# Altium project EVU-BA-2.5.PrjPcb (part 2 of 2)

## Sheet EVU-BA-2.5_Sheet4.SchDoc: EVU-BA-2.5
size A3; SheetNumber: 4; SheetTotal: 7; Prj: EVU-BA; Ver: 2.5; Ti: Kit Connectors
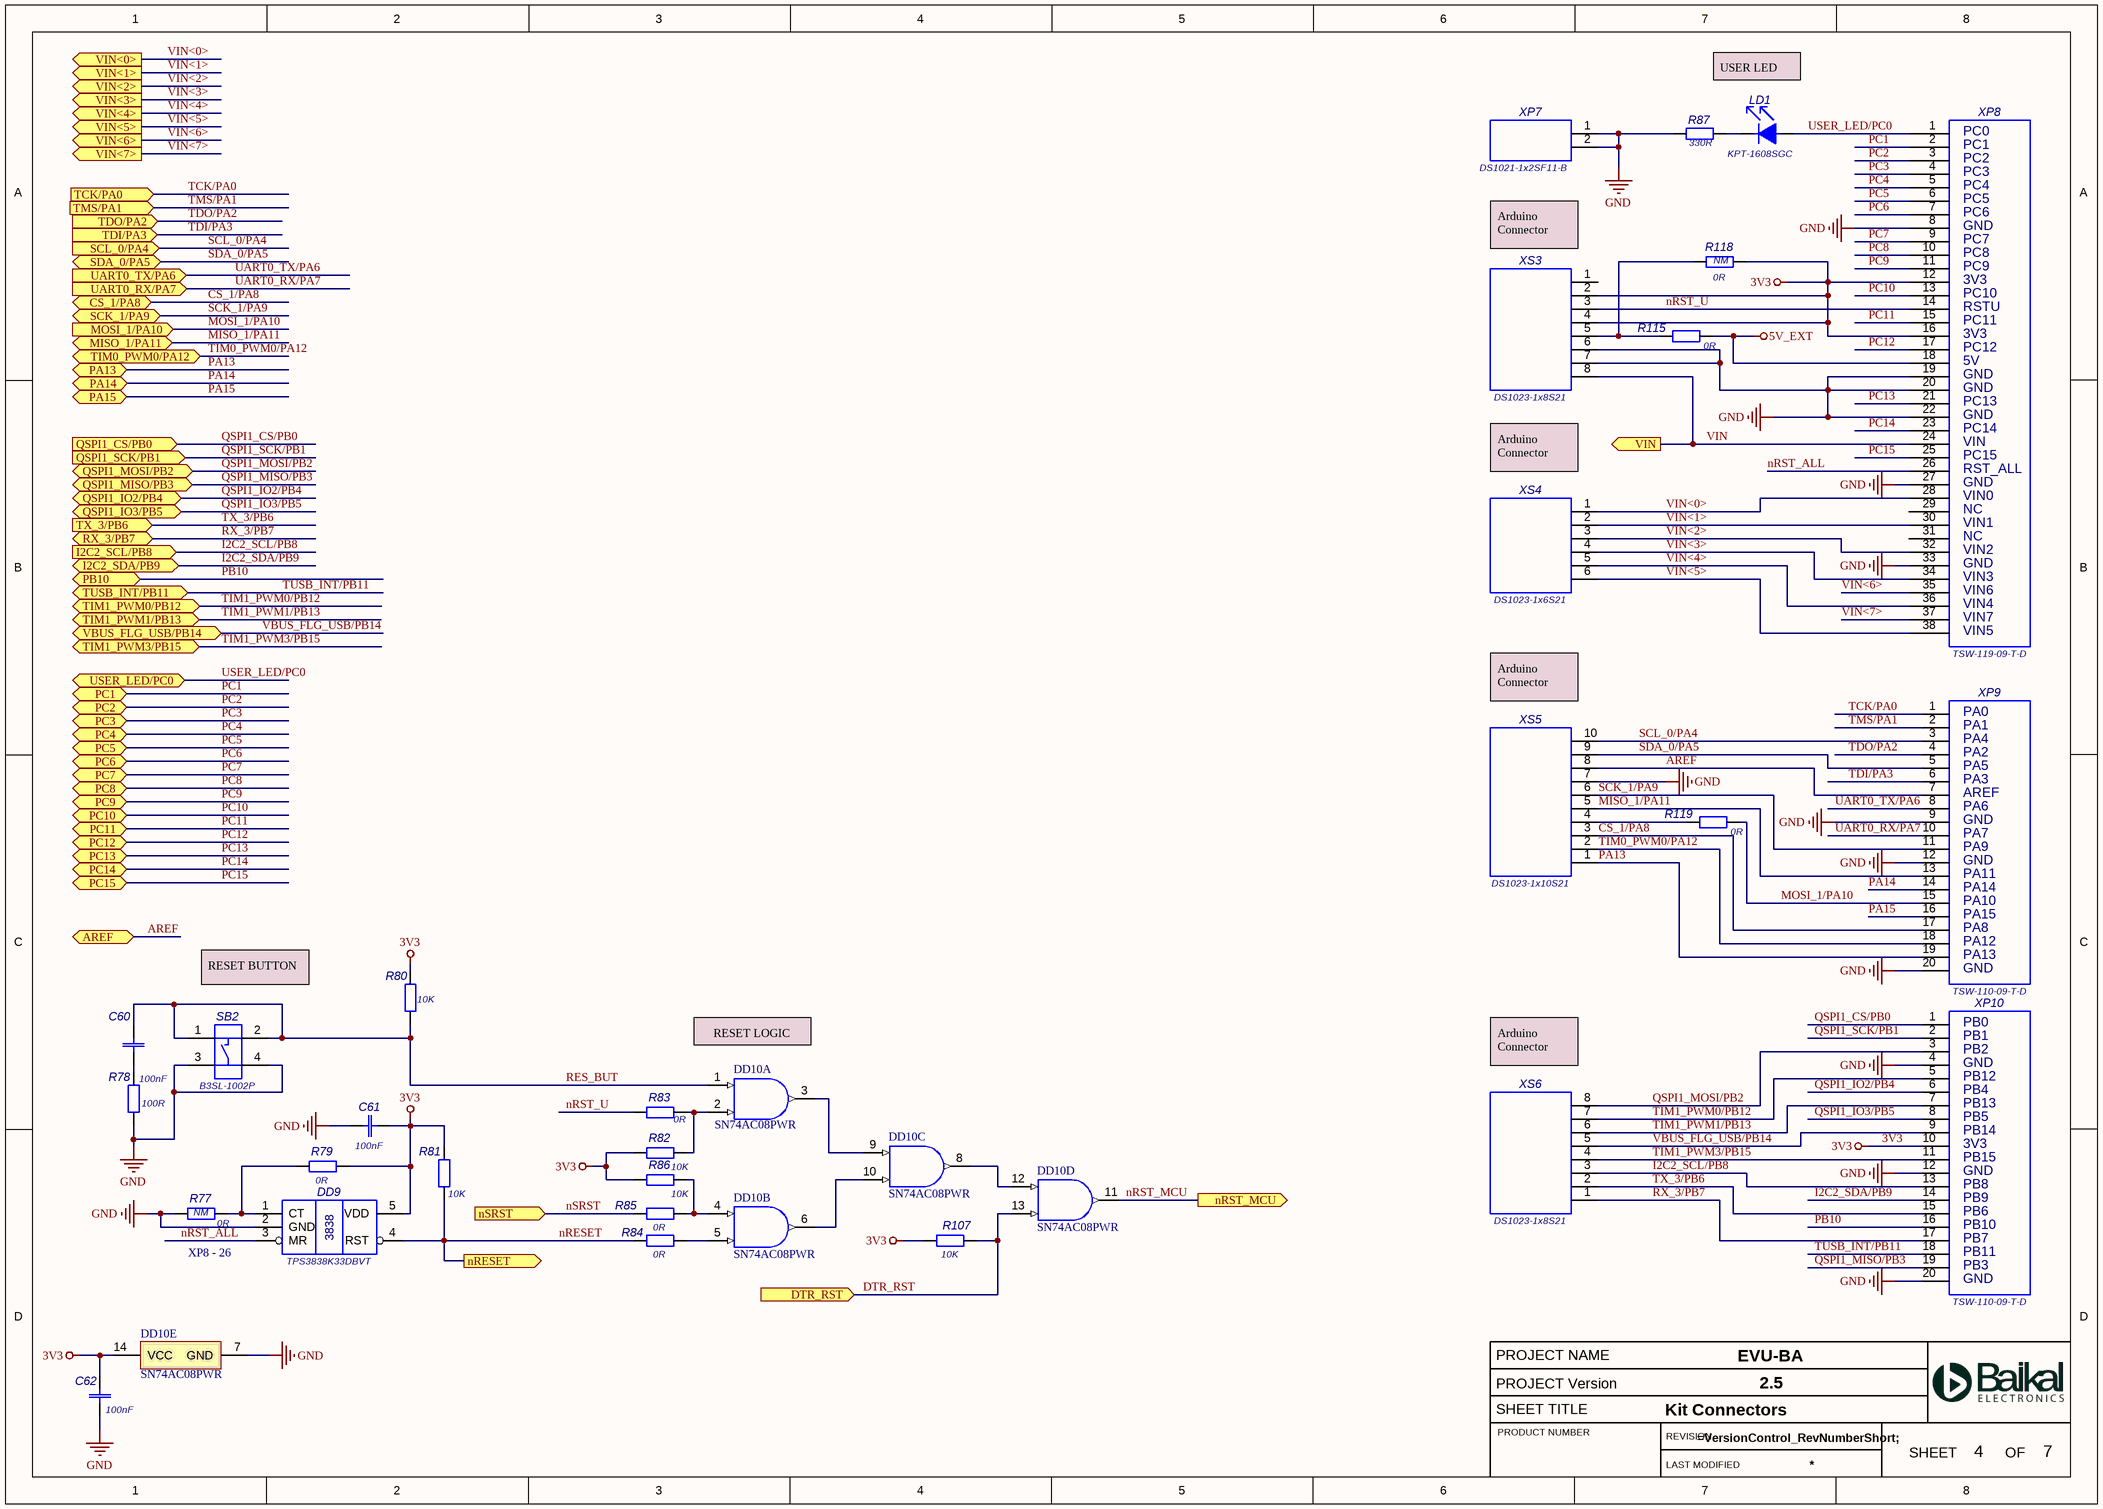
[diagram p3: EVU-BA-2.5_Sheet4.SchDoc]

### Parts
C60  value 100nF  [CAPC1608X80N]  (hidden comment: C0603C104K5RAC)
C61  value 100nF  [CAPC1608X80N]  (hidden comment: C0603C104K5RAC)
C62  value 100nF  [CAPC1608X80N]  (hidden comment: C0603C104K5RAC)
DD9  TPS3838K33DBVT  [SOT95P280X145-5N]
DD10  SN74AC08PWR  [PW0014A_L]  (parts A,B,C,D,E of 5)
LD1  KPT-1608SGC  [KPT1608X16X08X75N]
R77  value 0R  DNP: NM  [RESC1608X45N]  (hidden comment: CR0603-J/-000-E)
R78  value 100R  [RESC1608X45N]  (hidden comment: CR0603-JW-101-E)
R79  value 0R  [RESC1608X45N]  (hidden comment: CR0603-J/-000-E)
R80  value 10K  [RESC1608X45N]  (hidden comment: CR0603-JW-103-E)
R81  value 10K  [RESC1608X45N]  (hidden comment: CR0603-JW-103-E)
R82  value 10K  [RESC1608X45N]  (hidden comment: CR0603-JW-103-E)
R83  value 0R  [RESC1608X45N]  (hidden comment: CR0603-J/-000-E)
R84  value 0R  [RESC1608X45N]  (hidden comment: CR0603-J/-000-E)
R85  value 0R  [RESC1608X45N]  (hidden comment: CR0603-J/-000-E)
R86  value 10K  [RESC1608X45N]  (hidden comment: CR0603-JW-103-E)
R87  value 330R  [RESC1608X45N]  (hidden comment: CR0603-JW-331-E)
R107  value 10K  [RESC1608X45N]  (hidden comment: CR0603-JW-103-E)
R115  value 0R  [RESC1608X45N]  (hidden comment: CR0603-J/-000-E)
R118  value 0R  DNP: NM  [RESC1608X45N]  (hidden comment: CR0603-J/-000-E)
R119  value 0R  [RESC1608X45N]  (hidden comment: CR0603-J/-000-E)
SB2  B3SL-1002P  [B3SL-1002P]
XP7  DS1021-1x2SF11-B  [PLS2-254PX50X25X854N]
XP8  TSW-119-09-T-D  [PLD38-254PX4834X254X854N]
XP9  TSW-110-09-T-D  [PLD20-254PX2548X254X854N]
XP10  TSW-110-09-T-D  [PLD20-254PX2548X254X854N]
XS3  DS1023-1x8S21  [PBS8-254PX200X25X840N - duplicate]
XS4  DS1023-1x6S21  [PBS6-254PX152X25X840N - duplicate]
XS5  DS1023-1x10S21  [PBS10-254PX152X25X840N - duplicate]
XS6  DS1023-1x8S21  [PBS8-254PX200X25X840N - duplicate]

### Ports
AREF (bidir, see EVU-BA-2.5_Sheet1[3A], EVU-BA-2.5_Sheet2[3A]), CS_1/PA8 (bidir, see EVU-BA-2.5_Sheet1[3C], EVU-BA-2.5_Sheet2[5D]), DTR_RST (in, see EVU-BA-2.5_Sheet1[1D], EVU-BA-2.5_Sheet3[2C]), I2C2_SCL/PB8 (in, see EVU-BA-2.5_Sheet1[3B], EVU-BA-2.5_Sheet2[1D]), I2C2_SDA/PB9 (bidir, see EVU-BA-2.5_Sheet1[3B], EVU-BA-2.5_Sheet2[1D]), MISO_1/PA11 (bidir, see EVU-BA-2.5_Sheet1[3C], EVU-BA-2.5_Sheet2[5D]), MOSI_1/PA10 (in, see EVU-BA-2.5_Sheet1[3C], EVU-BA-2.5_Sheet2[5D]), nRESET (out, see EVU-BA-2.5_Sheet1[1D], EVU-BA-2.5_Sheet3[8B]), nRST_MCU (out, see EVU-BA-2.5_Sheet1[3A], EVU-BA-2.5_Sheet2[8A]), nSRST (in, see EVU-BA-2.5_Sheet1[1D], EVU-BA-2.5_Sheet3[2B]), PA13 (bidir, see EVU-BA-2.5_Sheet1[3C], EVU-BA-2.5_Sheet2[5D]), PA14 (bidir, see EVU-BA-2.5_Sheet1[3C], EVU-BA-2.5_Sheet2[5D]), PA15 (bidir, see EVU-BA-2.5_Sheet1[3C], EVU-BA-2.5_Sheet2[5D]), PB10 (bidir, see EVU-BA-2.5_Sheet1[3B], EVU-BA-2.5_Sheet2[1D]), PC1 (bidir, see EVU-BA-2.5_Sheet1[3B], EVU-BA-2.5_Sheet2[2D]), PC2 (bidir, see EVU-BA-2.5_Sheet1[3B], EVU-BA-2.5_Sheet2[2D]), PC3 (bidir, see EVU-BA-2.5_Sheet1[3B], EVU-BA-2.5_Sheet2[2D]), PC4 (bidir, see EVU-BA-2.5_Sheet1[3B], EVU-BA-2.5_Sheet2[2D]), PC5 (bidir, see EVU-BA-2.5_Sheet1[3B], EVU-BA-2.5_Sheet2[2D]), PC6 (bidir, see EVU-BA-2.5_Sheet1[3B], EVU-BA-2.5_Sheet2[2D]), PC7 (bidir, see EVU-BA-2.5_Sheet1[3B], EVU-BA-2.5_Sheet2[2C]), PC8 (bidir, see EVU-BA-2.5_Sheet1[3B], EVU-BA-2.5_Sheet2[2C]), PC9 (bidir, see EVU-BA-2.5_Sheet1[3B], EVU-BA-2.5_Sheet2[2C]), PC10 (bidir, see EVU-BA-2.5_Sheet1[3B], EVU-BA-2.5_Sheet2[2C]), PC11 (bidir, see EVU-BA-2.5_Sheet1[3B], EVU-BA-2.5_Sheet2[2C]), PC12 (bidir, see EVU-BA-2.5_Sheet1[3B], EVU-BA-2.5_Sheet2[2C]), PC13 (bidir, see EVU-BA-2.5_Sheet1[3B], EVU-BA-2.5_Sheet2[2C]), PC14 (bidir, see EVU-BA-2.5_Sheet1[3B], EVU-BA-2.5_Sheet2[2C]), PC15 (bidir, see EVU-BA-2.5_Sheet1[3B], EVU-BA-2.5_Sheet2[2C]), QSPI1_CS/PB0 (in, see EVU-BA-2.5_Sheet1[3C], EVU-BA-2.5_Sheet2[1D]), QSPI1_IO2/PB4 (bidir, see EVU-BA-2.5_Sheet1[3C], EVU-BA-2.5_Sheet2[1D]), QSPI1_IO3/PB5 (bidir, see EVU-BA-2.5_Sheet1[3C], EVU-BA-2.5_Sheet2[1D]), QSPI1_MISO/PB3 (bidir, see EVU-BA-2.5_Sheet1[3C], EVU-BA-2.5_Sheet2[1D]), QSPI1_MOSI/PB2 (bidir, see EVU-BA-2.5_Sheet1[3C], EVU-BA-2.5_Sheet2[1D]), QSPI1_SCK/PB1 (in, see EVU-BA-2.5_Sheet1[3C], EVU-BA-2.5_Sheet2[1D]), RX_3/PB7 (bidir, see EVU-BA-2.5_Sheet1[3B], EVU-BA-2.5_Sheet2[1D]), SCK_1/PA9 (bidir, see EVU-BA-2.5_Sheet1[3C], EVU-BA-2.5_Sheet2[5D]), SCL_0/PA4 (in, see EVU-BA-2.5_Sheet1[3D], EVU-BA-2.5_Sheet2[5D], EVU-BA-2.5_Sheet3[1B]), SDA_0/PA5 (bidir, see EVU-BA-2.5_Sheet1[3D], EVU-BA-2.5_Sheet2[5D]), TCK/PA0 (in, see EVU-BA-2.5_Sheet1[1D], EVU-BA-2.5_Sheet2[5D], EVU-BA-2.5_Sheet3[1C]), TDI/PA3 (in, see EVU-BA-2.5_Sheet1[1D], EVU-BA-2.5_Sheet2[5D], EVU-BA-2.5_Sheet3[1C]), TDO/PA2 (in, see EVU-BA-2.5_Sheet1[1D], EVU-BA-2.5_Sheet2[5D], EVU-BA-2.5_Sheet3[1C]), TIM0_PWM0/PA12 (bidir, see EVU-BA-2.5_Sheet1[3C], EVU-BA-2.5_Sheet2[5D]), TIM1_PWM0/PB12 (bidir, see EVU-BA-2.5_Sheet1[3B], EVU-BA-2.5_Sheet2[1D]), TIM1_PWM1/PB13 (bidir, see EVU-BA-2.5_Sheet1[3B], EVU-BA-2.5_Sheet2[1D]), TIM1_PWM3/PB15 (bidir, see EVU-BA-2.5_Sheet1[3B], EVU-BA-2.5_Sheet2[1D]), TMS/PA1 (in, see EVU-BA-2.5_Sheet1[1D], EVU-BA-2.5_Sheet2[5D], EVU-BA-2.5_Sheet3[1B]), TUSB_INT/PB11 (bidir, see EVU-BA-2.5_Sheet1[3B], EVU-BA-2.5_Sheet2[1D]), TX_3/PB6 (in, see EVU-BA-2.5_Sheet1[3C], EVU-BA-2.5_Sheet2[1D]), UART0_RX/PA7 (in, see EVU-BA-2.5_Sheet1[3D], EVU-BA-2.5_Sheet2[5D], EVU-BA-2.5_Sheet3[1C]), UART0_TX/PA6 (in, see EVU-BA-2.5_Sheet1[3D], EVU-BA-2.5_Sheet2[5D], EVU-BA-2.5_Sheet3[1C]), USER_LED/PC0 (bidir, see EVU-BA-2.5_Sheet1[3B], EVU-BA-2.5_Sheet2[2D]), VBUS_FLG_USB/PB14 (bidir, see EVU-BA-2.5_Sheet1[3B]), VIN (out, see EVU-BA-2.5_Sheet1[3A], EVU-BA-2.5_Sheet5[8B]), VIN<0> (out, see EVU-BA-2.5_Sheet1[3C], EVU-BA-2.5_Sheet2[4C]), VIN<1> (out, see EVU-BA-2.5_Sheet1[3C], EVU-BA-2.5_Sheet2[4C]), VIN<2> (out, see EVU-BA-2.5_Sheet1[3C], EVU-BA-2.5_Sheet2[4C]), VIN<3> (out, see EVU-BA-2.5_Sheet1[3C], EVU-BA-2.5_Sheet2[4C]), VIN<4> (out, see EVU-BA-2.5_Sheet1[3C], EVU-BA-2.5_Sheet2[4C]), VIN<5> (out, see EVU-BA-2.5_Sheet1[3C], EVU-BA-2.5_Sheet2[4C]), VIN<6> (out, see EVU-BA-2.5_Sheet1[3C], EVU-BA-2.5_Sheet2[4C]), VIN<7> (out, see EVU-BA-2.5_Sheet1[3C], EVU-BA-2.5_Sheet2[4C])

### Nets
3V3: C61.2 C62.2 DD9.5(VDD) DD10.14(VCC) R79.2 R80.2 R81.2 R82.2 R86.2 R107.2 R118.2 XP8.12 XP8.16 XP10.10 XS3.2 XS3.4
5V_EXT: R115.2 XP8.18
GND: C61.1 C62.1 DD9.2(GND) DD10.7(GND) R77.1 R78.1 R87.1 SB2.3 SB2.4 XP7.1 XP7.2 XP8.8 XP8.19 XP8.20 XP8.22 XP8.27 XP8.33 XP9.9 XP9.12 XP9.20 XP10.4 XP10.12 XP10.20 XS3.6 XS3.7 XS5.7
AREF: XP9.7 XS5.8 ; port AREF
CS_1/PA8: XP9.17 XS5.3 ; port CS_1/PA8
DTR_RST: DD10.13(4B) R107.1 ; port DTR_RST
I2C2_SCL/PB8: XP10.13 XS6.3 ; port I2C2_SCL/PB8
I2C2_SDA/PB9: XP10.14 ; port I2C2_SDA/PB9
MISO_1/PA11: XP9.13 XS5.5 ; port MISO_1/PA11
MOSI_1/PA10: R119.2 XP9.15 ; port MOSI_1/PA10
nRESET: DD9.4(RST) R81.1 R84.2 ; port nRESET
nRST_ALL: DD9.3(MR) XP8.26
nRST_MCU: DD10.11(4Y) ; port nRST_MCU
nRST_U: R83.2 XP8.14 XS3.3
nSRST: R85.1 ; port nSRST
PA13: XP9.19 XS5.1 ; port PA13
PA14: XP9.14 ; port PA14
PA15: XP9.16 ; port PA15
PB10: XP10.16 ; port PB10
PC1: XP8.2 ; port PC1
PC2: XP8.3 ; port PC2
PC3: XP8.4 ; port PC3
PC4: XP8.5 ; port PC4
PC5: XP8.6 ; port PC5
PC6: XP8.7 ; port PC6
PC7: XP8.9 ; port PC7
PC8: XP8.10 ; port PC8
PC9: XP8.11 ; port PC9
PC10: XP8.13 ; port PC10
PC11: XP8.15 ; port PC11
PC12: XP8.17 ; port PC12
PC13: XP8.21 ; port PC13
PC14: XP8.23 ; port PC14
PC15: XP8.25 ; port PC15
QSPI1_CS/PB0: XP10.1 ; port QSPI1_CS/PB0
QSPI1_IO2/PB4: XP10.6 ; port QSPI1_IO2/PB4
QSPI1_IO3/PB5: XP10.8 ; port QSPI1_IO3/PB5
QSPI1_MISO/PB3: XP10.19 ; port QSPI1_MISO/PB3
QSPI1_MOSI/PB2: XP10.3 XS6.8 ; port QSPI1_MOSI/PB2
QSPI1_SCK/PB1: XP10.2 ; port QSPI1_SCK/PB1
RES_BUT: C60.1 DD10.1(1A) R80.1 SB2.1 SB2.2
RX_3/PB7: XP10.17 XS6.1 ; port RX_3/PB7
SCK_1/PA9: XP9.11 XS5.6 ; port SCK_1/PA9
SCL_0/PA4: XP9.3 XS5.10 ; port SCL_0/PA4
SDA_0/PA5: XP9.5 XS5.9 ; port SDA_0/PA5
TCK/PA0: XP9.1 ; port TCK/PA0
TDI/PA3: XP9.6 ; port TDI/PA3
TDO/PA2: XP9.4 ; port TDO/PA2
TIM0_PWM0/PA12: XP9.18 XS5.2 ; port TIM0_PWM0/PA12
TIM1_PWM0/PB12: XP10.5 XS6.7 ; port TIM1_PWM0/PB12
TIM1_PWM1/PB13: XP10.7 XS6.6 ; port TIM1_PWM1/PB13
TIM1_PWM3/PB15: XP10.11 XS6.4 ; port TIM1_PWM3/PB15
TMS/PA1: XP9.2 ; port TMS/PA1
TUSB_INT/PB11: XP10.18 ; port TUSB_INT/PB11
TX_3/PB6: XP10.15 XS6.2 ; port TX_3/PB6
UART0_RX/PA7: XP9.10 ; port UART0_RX/PA7
UART0_TX/PA6: XP9.8 ; port UART0_TX/PA6
USER_LED/PC0: LD1.1 XP8.1 ; port USER_LED/PC0
VBUS_FLG_USB/PB14: XP10.9 XS6.5 ; port VBUS_FLG_USB/PB14  [project net nVBUS_FLG_USB/PB14]
VIN: XP8.24 XS3.8 ; port VIN
VIN<0>: XP8.28 XS4.1 ; port VIN<0>
VIN<1>: XP8.30 XS4.2 ; port VIN<1>
VIN<2>: XP8.32 XS4.3 ; port VIN<2>
VIN<3>: XP8.34 XS4.4 ; port VIN<3>
VIN<4>: XP8.36 XS4.5 ; port VIN<4>
VIN<5>: XP8.38 XS4.6 ; port VIN<5>
VIN<6>: XP8.35 ; port VIN<6>
VIN<7>: XP8.37 ; port VIN<7>
NetC60_2: C60.2 R78.2
NetDD9_1: DD9.1(CT) R77.2 R79.1
NetDD10_2: DD10.2(1B) R82.1 R83.1
NetDD10_3: DD10.3(1Y) DD10.9(3A)
NetDD10_4: DD10.4(2A) R85.2 R86.1
NetDD10_5: DD10.5(2B) R84.1
NetDD10_6: DD10.6(2Y) DD10.10(3B)
NetDD10_8: DD10.8(3Y) DD10.12(4A)
NetLD1_2: LD1.2 R87.2
NetR115_1: R115.1 R118.1 XS3.5
NetR119_1: R119.1 XS5.4

Not connected (* = marked no-connect by the designer): XP8 29 31; XS3 1

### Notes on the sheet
- USER LED
- (near XP8) PC0
- (near XP8) PC1
- (near XP8) PC2
- (near XP8) PC3
- Arduino Connector
- (near XP8) PC4
- (near XP8) PC5
- (near XP8) GND
- (near XP8) PC6
- (near XP8) PC7
- (near XP8) PC8
- (near XP8) PC9
- (near XP8) 3V3
- (near XP8) PC10
- (near XP8) RSTU
- (near XP8) PC11
- (near XP8) PC12
- (near XP8) 5V
- (near XP8) PC13
- (near XP8) PC14
- (near XP8) VIN
- (near XP8) PC15
- (near XP8) RST_ALL
- (near XP8) VIN0
- (near XP8) NC
- (near XP8) VIN1
- (near XP8) VIN2
- (near XP8) VIN3
- (near XP8) VIN4
- (near XP8) VIN5
- (near XP8) VIN6
- (near XP8) VIN7
- (near XS5) Arduino Connector
- (near XP9) PA0
- (near XP9) PA1
- (near XP9) PA2
- (near XP9) PA3
- (near XP9) PA4
- (near XP9) PA5
- (near XP9) PA6
- (near XP9) AREF
- (near XP9) GND
- (near XP9) PA7
- (near XP9) PA9
- (near XP9) PA11
- (near XP9) PA14
- (near XP9) PA10
- (near XP9) PA15
- RESET BUTTON
- (near XP9) PA8
- (near XP9) PA12
- (near XP9) PA13
- (near DD10) RESET LOGIC
- (near XP10) PB0
- (near XP10) PB1
- (near XP10) PB2
- (near XS6) Arduino Connector
- (near XP10) GND
- (near XP10) PB12
- (near XP10) PB4
- (near XP10) PB13
- (near XP10) PB5
- (near XP10) PB14
- (near XP10) 3V3
- (near XP10) PB15
- (near XP10) PB8
- XP8 - 26
- (near XP10) PB9
- (near XP10) PB6
- (near XP10) PB10
- (near XP10) PB7
- (near XP10) PB11
- (near XP10) PB3

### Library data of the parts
C60-C62 = C0603C104K5RAC: 0603 X7R 0,1 uF ±10% 50V; Manufacturer: "Kemet"; NOM: 0603 X7R 100nF ±10% 50V; Value Ru: 0,1 мкФ
DD9 = TPS3838K33DBVT: Supervisor Integrated Circuit; Manufacturer: "Texas Instruments"
DD10 = SN74AC08PWR: Quadruple 2-Input Positive-AND Gates, PW0014A, LARGE T&R; Manufacturer: "Texas Instruments"; Technology Family: AC; VCC(Min)(V): 2; Input Type: CMOS; Rating: Catalog; F @ Nom Voltage(Max)(Mhz): 100; Schmitt Trigger: No; Output Drive (IOL/IOH)(Max)(mA): -24/24; Bits(#): 4; Voltage(Nom)(V): 3.3,5; tpd @ Nom Voltage(Max)(ns): 10,8.5; VCC(Max)(V): 6; ICC @ Nom Voltage(Max)(mA): 0.02
LD1 = KPT-1608SGC: 0603 LED Diod SMD Green; Manufacturer: "Kingbright"; TKE: 0603
R77 R79 R83-R85 R115 R118 R119 = CR0603-J/-000-E: 0603 0 Ohm 0,1W; Manufacturer: "Bourns"; TKE: 0603; MARK: 000; NOM: 0603 0R; Value Ru: 0 Ом; Replacement: RC0603JR-070RL
R78 = CR0603-JW-101-E: 0603 100 Ohm±5% 0,1W; Manufacturer: "Bourns"; TKE: 0603; MARK: 101; Power_Voltage: 0,1W; NOM: 0603 100R ±5% 0,1W; Tolerance: ±5%; Value Ru: 100 Ом
R80-R82 R86 R107 = CR0603-JW-103-E: 0603 10 kOhm±5% 0,1W; Manufacturer: "Bourns"; TKE: 0603; MARK: 103; Power_Voltage: 0,1W; NOM: 0603 10K ±5% 0,1W; Tolerance: ±5%; Value Ru: 10 кОм
R87 = CR0603-JW-331-E: 0603 330 Ohm ±5% 0.1W; Manufacturer: "Bourns"; TKE: 0603; MARK: 330; Power_Voltage: 0,1 Вт; NOM: 0603 330R ±5% 0,1 Вт; Value Ru: 330 Ом
SB2 = B3SL-1002P: Surface-mounting Sealed Tactile Switch; ManufacturerPartNumber: B3SL-1022P; Manufacturer: "Omron Corporation"
XP7 = DS1021-1x2SF11-B: Connector 2.54 pitch, 1 row, 8.54 height, 2 pins per row; Manufacturer: "Connfly"
XP8 = TSW-119-09-T-D: Connector 2.54 pitch, 2 rows, 18.54 height, 19 pins per row; Manufacturer: "Samtec"
XP9 XP10 = TSW-110-09-T-D: Connector 2.54 pitch, 2 rows, 18.54 height, 10 pins per row; Manufacturer: "Samtec"
XS3 XS6 = DS1023-1x8S21: Connector 2.54 pitch, 1 row, 8.54 height, 8 pins per row; ManufacturerPartNumber: DS-1023-1x8 (PBS-8); Manufacturer: "Connfly"
XS4 = DS1023-1x6S21: Connector 2.54 pitch, 1 row, 8.54 height, 6 pins per row; ManufacturerPartNumber: DS1023-1x6S21(PBS-6); Manufacturer: "Connfly"
XS5 = DS1023-1x10S21: Connector 2.54 pitch, 1 row, 8.54 height, 10 pins per row; ManufacturerPartNumber: DS1023-1X10S21 (PBS-10); Manufacturer: "Connfly"

## Sheet EVU-BA-2.5_Sheet5.SchDoc: EVU-BA-2.5
size A3; SheetNumber: 5; SheetTotal: 7; Prj: EVU-BA; Ver: 2.5; Ti: Power supply
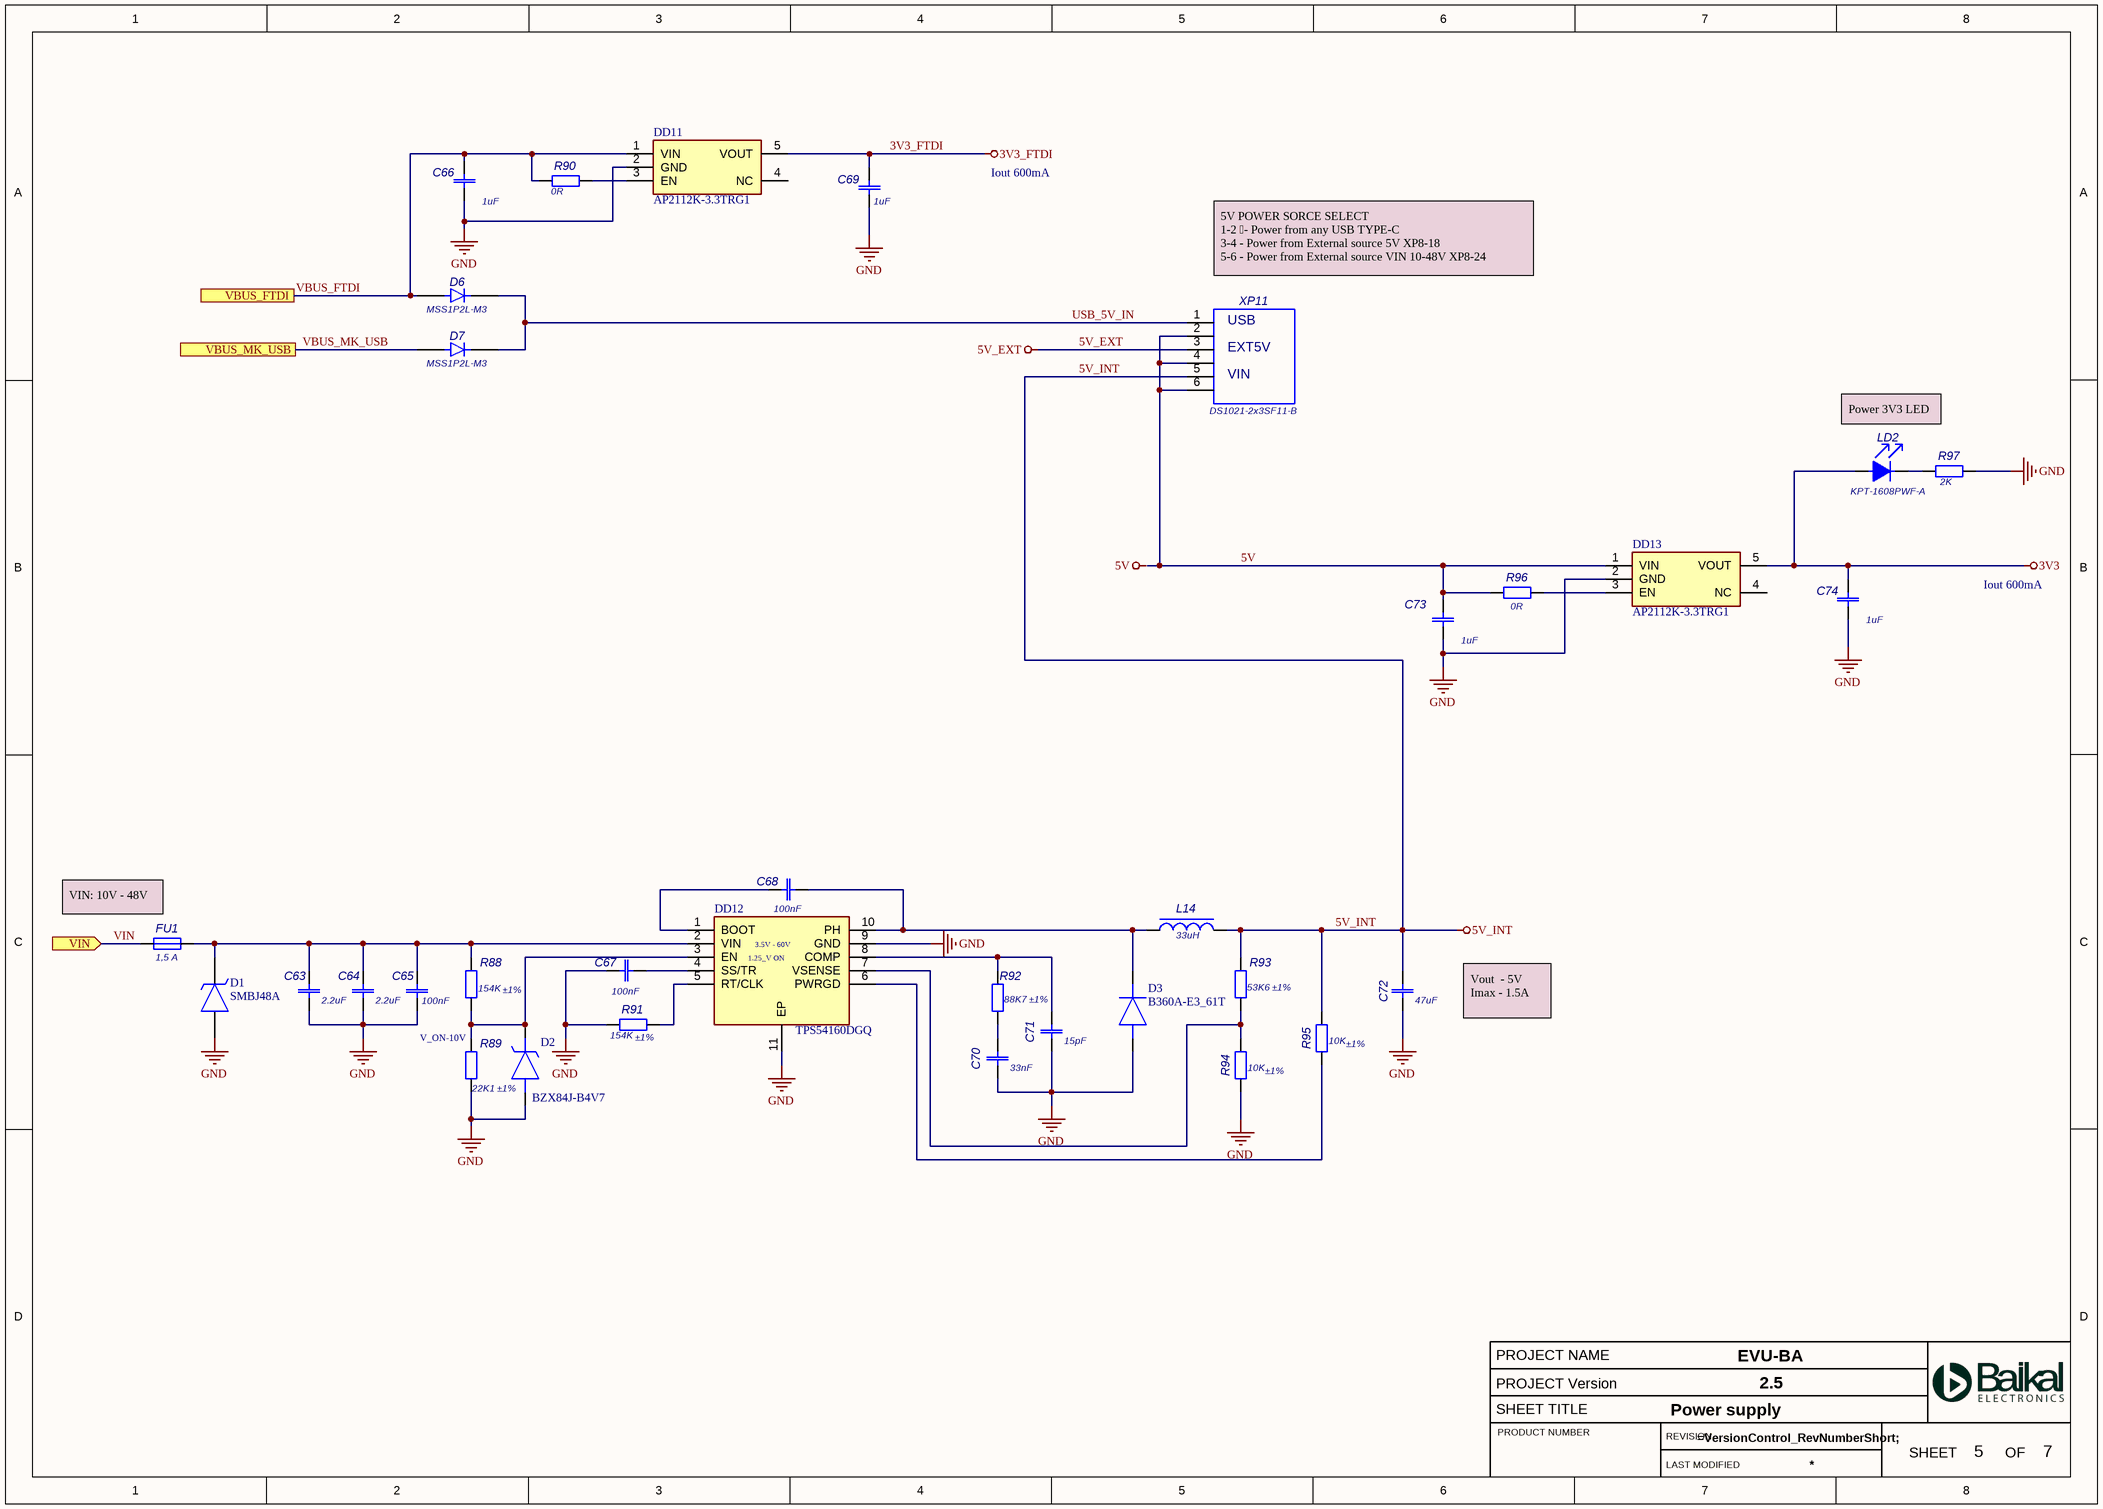
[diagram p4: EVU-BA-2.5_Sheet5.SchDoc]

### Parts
C63  value 2.2uF  [CAPC3225X200N]  (hidden comment: GCJ32DR72A225KA01)
C64  value 2.2uF  [CAPC3225X200N]  (hidden comment: GCJ32DR72A225KA01)
C65  value 100nF  [CAPC1608X80N]  (hidden comment: C0603C104K5RAC)
C66  value 1uF  [CAPC1608X80N]  (hidden comment: GRM188R71C105KA12D)
C67  value 100nF  [CAPC1608X80N]  (hidden comment: C0603C104K5RAC)
C68  value 100nF  [CAPC1608X80N]  (hidden comment: C0603C104K5RAC)
C69  value 1uF  [CAPC1608X80N]  (hidden comment: GRM188R71C105KA12D)
C70  value 33nF  [CAPC1608X80N]  (hidden comment: GRM188R71H333KA61D)
C71  value 15pF  [CAPC1608X80N]  (hidden comment: C0603C150K4RAC)
C72  value 47uF  [CAPC3225X250N]  (hidden comment: GRM32ER71A476ME15L)
C73  value 1uF  [CAPC1608X80N]  (hidden comment: GRM188R71C105KA12D)
C74  value 1uF  [CAPC1608X80N]  (hidden comment: GRM188R71C105KA12D)
D1  SMBJ48A  [SMBJ12A]
D2  BZX84J-B4V7  [SOD2512X80N]
D3  B360A-E3_61T  [DIOM5127X229N]
D6  MSS1P2L-M3  [MicroSMP27X14X7]
D7  MSS1P2L-M3  [MicroSMP27X14X7]
DD11  AP2112K-3.3TRG1  [SOT95P285X140-5N]
DD12  TPS54160DGQ  [SOP50P490X110-11N]
DD13  AP2112K-3.3TRG1  [SOT95P285X140-5N]
FU1  value 1,5 A  [FUSE466X32X15X60N]  (hidden comment: 046601.5NRHF)
L14  Value Eng: 33uH  [CDRH105RNP]  (hidden comment: CDRH105RNP-330NC)
LD2  KPT-1608PWF-A  [KPT1608X16X08X75N]
R88  value 154K  Tolerance: ±1%  [RESC1608X45N]  (hidden comment: CR0603-FX-1543-E)
R89  value 22K1  Tolerance: ±1%  [RESC1608X45N]  (hidden comment: CR0603-FX-2212-E)
R90  value 0R  [RESC1608X45N]  (hidden comment: CR0603-J/-000-E)
R91  value 154K  Tolerance: ±1%  [RESC1608X45N]  (hidden comment: CR0603-FX-1543-E)
R92  value 88K7  Tolerance: ±1%  [RESC1608X45N]  (hidden comment: CR0603-FX-8872-E)
R93  value 53K6  Tolerance: ±1%  [RESC1608X45N]  (hidden comment: CR0603-FX-5362-E)
R94  value 10K  Tolerance: ±1%  [RESC1608X45N]  (hidden comment: CR0603-FX-1002-E)
R95  value 10K  Tolerance: ±1%  [RESC1608X45N]  (hidden comment: CR0603-FX-1002-E)
R96  value 0R  [RESC1608X45N]  (hidden comment: CR0603-J/-000-E)
R97  value 2K  [RESC1608X45N]  (hidden comment: CR0603-JW-202-E)
XP11  DS1021-2x3SF11-B  [PLD6-254PX762X508X854N]

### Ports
VBUS_FTDI (see EVU-BA-2.5_Sheet1[7A], EVU-BA-2.5_Sheet3[5C]), VBUS_MK_USB (see EVU-BA-2.5_Sheet1[7A], EVU-BA-2.5_Sheet2[5C]), VIN (in, see EVU-BA-2.5_Sheet1[7A], EVU-BA-2.5_Sheet4[2C])

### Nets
3V3: C74.2 DD13.5(VOUT) LD2.1
3V3_FTDI: C69.2 DD11.5(VOUT)
5V: C73.2 DD13.1(VIN) R96.1 XP11.2 XP11.4 XP11.6
5V_EXT: XP11.3
5V_INT: C72.2 L14.2 R93.2 R95.2 XP11.5
GND: C63.1 C64.1 C65.1 C66.1 C67.1 C69.1 C70.1 C71.1 C72.1 C73.1 C74.1 D1.2(A) D2.2(A) D3.2(A) DD11.2(GND) DD12.9(GND) DD12.11(EP) DD13.2(GND) R89.1 R91.1 R94.1 R97.2
USB_5V_IN: D6.1(C) D7.1(C) XP11.1
VBUS_FTDI: C66.2 D6.2(A) DD11.1(VIN) R90.1 ; port VBUS_FTDI
VBUS_MK_USB: D7.2(A) ; port VBUS_MK_USB
VIN: FU1.1 ; port VIN
NetC63_2: C63.2 C64.2 C65.2 D1.1(K) DD12.2(VIN) FU1.2 R88.2
NetC67_2: C67.2 DD12.4(SS/TR)
NetC68_1: C68.1 DD12.1(BOOT)
NetC68_2: C68.2 D3.1(K) DD12.10(PH) L14.1
NetC70_2: C70.2 R92.1
NetC71_2: C71.2 DD12.8(COMP) R92.2
NetD2_1: D2.1(K) DD12.3(EN) R88.1 R89.2
NetDD11_3: DD11.3(EN) R90.2
NetDD12_5: DD12.5(RT/CLK) R91.2
NetDD12_6: DD12.6(PWRGD) R95.1
NetDD12_7: DD12.7(VSENSE) R93.1 R94.2
NetDD13_3: DD13.3(EN) R96.2
NetLD2_2: LD2.2 R97.1

Not connected (* = marked no-connect by the designer): DD11 4(NC); DD13 4(NC)

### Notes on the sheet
- Iout 600mA
- (near XP11) 5V POWER SORCE SELECT
  1-2 - Power from any USB TYPE-C
  3-4 - Power from External source 5V XP8-18
  5-6 - Power from External source VIN 10-48V XP8-24
- (near XP11) VIN
- (near XP11) USB
- (near XP11) EXT5V
- Power 3V3 LED
- (near FU1) VIN: 10V - 48V
- (near DD12) 1.25_V ON
- (near DD12) 3.5V - 60V
- (near R89) V_ON-10V
- Vout  - 5V
  Imax - 1.5A
- Labels drawn without touching a wire or pin: 5V

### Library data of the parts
C63 C64 = GCJ32DR72A225KA01: 1210 X7R 2,2 uF±10% 100V; Manufacturer: "Murata"; Tolerance: ±10%; NOM: 1210 X7R 2.2uF ±10% 100V; Value Ru: 2,2 мкФ
C65 C67 C68 = C0603C104K5RAC: as C60-C62 on sheet EVU-BA-2.5_Sheet4
C66 C69 C73 C74 = GRM188R71C105KA12D: 0603 X7R 1,0 uF±10% 16V; Manufacturer: "Murata"; Tolerance: ±10%; NOM: 0603 X7R 1uF ±10% 16V; Value Ru: 1,0 мкФ
C70 = GRM188R71H333KA61D: 0603 X7R 33 nF±10% 50V; Manufacturer: "Murata"; Tolerance: ±10%; Value Ru: 33000 пФ
C71 = C0603C150K4RAC: 0603 X7R 15 pF±10% 16V; ManufacturerPartNumber: C0603C100K4RAC; Manufacturer: "Kemet"; Tolerance: ±10%; Value Ru: 15 пФ; Replacement: 06035A150JAT2A
C72 = GRM32ER71A476ME15L: 1210 X7R 47 uF±20% 10V; Manufacturer: "Murata"; Tolerance: ±20%; Value Ru: 47 мкФ
D1 = SMBJ48A-TR: TVS Diode (Uni-directional); Manufacturer_Name: STMicroelectronics; Manufacturer: "STMicroelectronics"; Power_Voltage: Vrm 48V, Irm 0.2A; TKE: SMB(DO-214AA-2)
D2 = BZX84J-B4V7: Zener Diode Vstab=4.7V, Iforvard=100mA, SOD-323, 0.55W; Manufacturer: "Nexperia"
D3 = B360A-E3_61T: Schottky Diode  60V 3.0A; Manufacturer_Part_Number: B360A-E3/61T; Manufacturer: "Vishay"
D6 D7 = MSS1P2L-M3: Schottky Diod; Manufacturer: "Vishay"
DD11 DD13 = AP2112K-3.3TRG1: LDO voltage regulator Vout -3.3V, Iout - 0.6A max, Vout accuracy ±1.5%; Manufacturer_Name: Diodes Incorporated; Manufacturer: "Diodes"
DD12 = TPS54160DGQ: DC-DC STEP DOWN Converter 1.5-A, 60V; Manufacturer: "Texas Instruments"
FU1 = 046601.5NRHF: Fuse SMD 1,5A 63V; Manufacturer: "Littelfuse"; MARK: K
L14 = CDRH105RNP-330NC: 33 uH±30% 2.75A 65mOhm SMD; Manufacturer: "Sumida"; Power_Voltage: 2,4 A; NOM: 33 мкГн  2,4 A; Value: 33 мкГн
LD2 = KPT-1608PWF-A: 0603 LED Diod SMD White; Manufacturer: "Kingbright"; TKE: 0603
R88 R91 = CR0603-FX-1543-E: 0603 154 kOhm±1% 0,1W; Manufacturer: "Bourns"; TKE: 0603; MARK: 19D; Power_Voltage: 0,1 Вт; NOM: 0603 154K ±1% 0,1 Вт; Value Ru: 154 кОм
R89 = CR0603-FX-2212-E: 0603 22,1 kOhm±1% 0,1W; Manufacturer: "Bourns"; TKE: 0603; MARK: 34C; Power_Voltage: 0,1 Вт; NOM: 0603 22K1 ±1% 0,1 Вт; Value Ru: 22,1 кОм
R90 R96 = CR0603-J/-000-E: as R77 on sheet EVU-BA-2.5_Sheet4
R92 = CR0603-FX-8872-E: 0603 88,7 kOhm±1% 0,1W; Manufacturer: "Bourns"; TKE: 0603; Power_Voltage: 0,1W; NOM: 0603 88K7 ±1% 0,1W; Value Ru: 88,7 кОм
R93 = CR0603-FX-5362-E: 0603 53,6 kOhm ±1% 0,1W; Manufacturer: "Bourns"; TKE: 0603; Power_Voltage: 0,1W; NOM: 0603 53K6 ±1% 0,1W; Value Ru: 53,6 кОм
R94 R95 = CR0603-FX-1002-E: 0603 10 kOhm±1% 0,1W; Manufacturer: "Bourns"; TKE: 0603; MARK: 01C; Power_Voltage: 0,1 Вт; NOM: 0603 10K ±1% 0,1 Вт; Value Ru: 10 кОм
R97 = CR0603-JW-202-E: 0603 2 kOhm±5% 0.1W; Manufacturer: "Bourns"; TKE: 0603; MARK: 202; Power_Voltage: 0,1 Вт; NOM: 0603 2K ±5% 0,1 Вт; Tolerance: ±5%; Value Ru: 2 кОм
XP11 = DS1021-2x3SF11-B: Connector 2.54 pitch, 2 rows, 8.54 height, 3 pins per row; Manufacturer: "Connfly"

## Sheet EVU-BA-2.5_Sheet6.SchDoc: EVU-BA-2.5
size A3; SheetNumber: 6; SheetTotal: 7; Prj: EVU-BA; Ver: 2.5; TI: Schematic block diagram
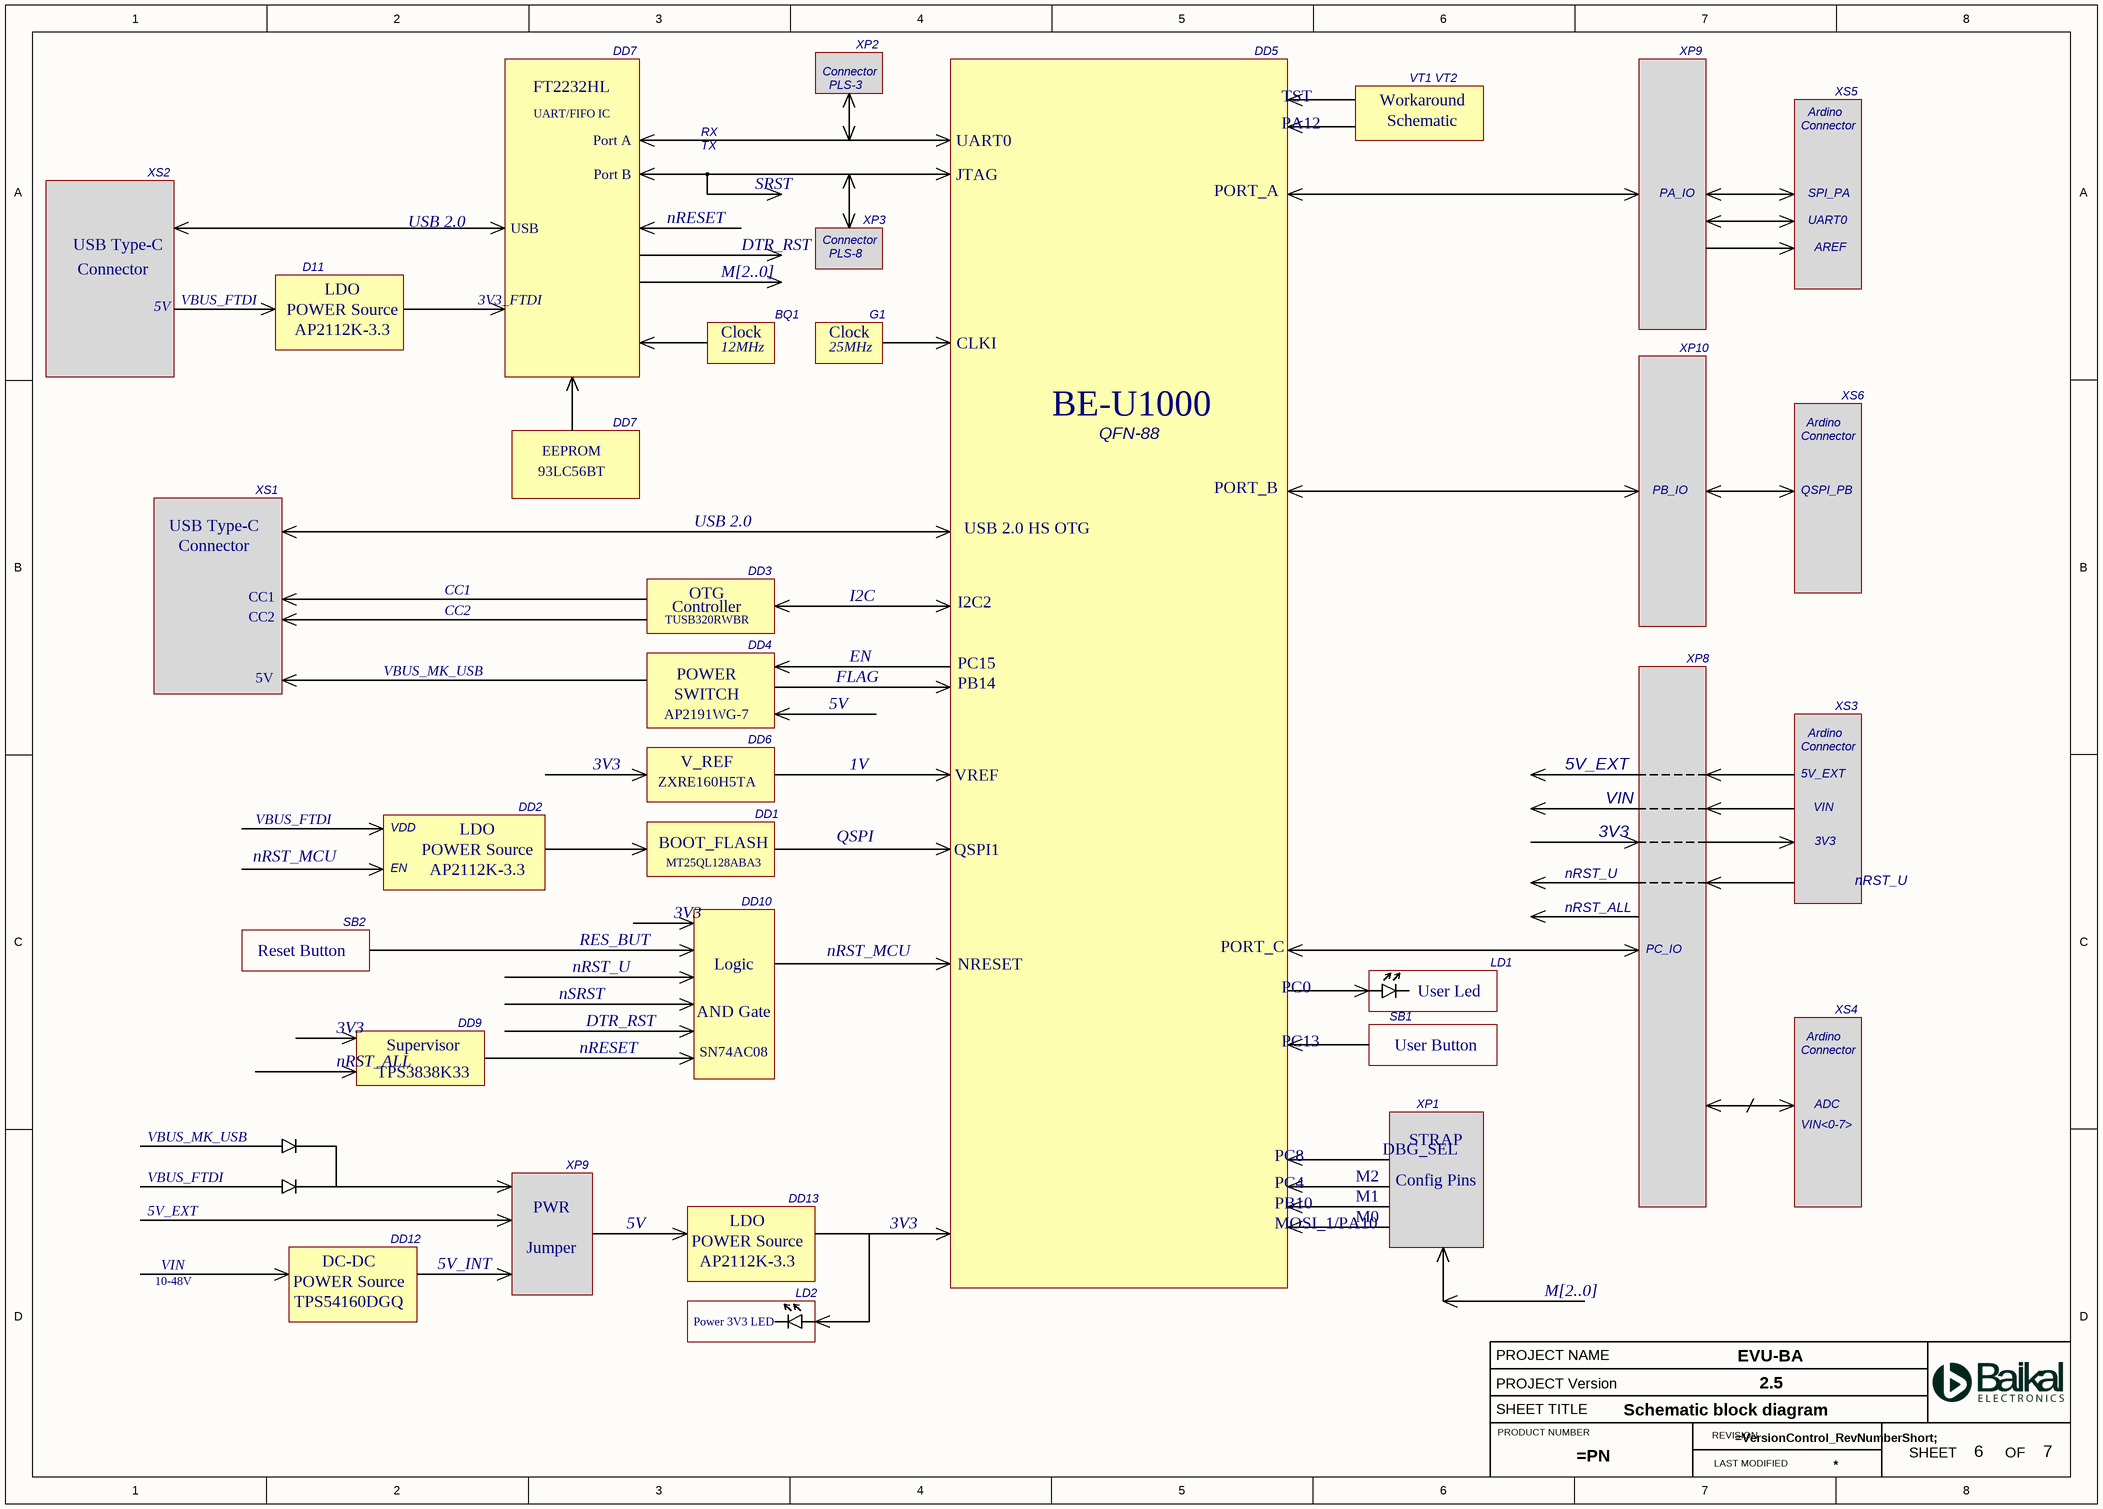
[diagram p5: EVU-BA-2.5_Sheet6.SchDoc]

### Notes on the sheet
- XP2
- FT2232HL
- UART/FIFO IC
- DD7
- Connector
- PLS-3
- DD5
- TST
- VT1 VT2
- Workaround
- XP9
- XS5
- XS2
- Port A
- Port B
- RX
- TX
- JTAG
- UART0
- PA12
- Schematic
- Ardino
- USB 2.0
- USB
- nRESET
- SRST
- XP3
- PORT_A
- PA_IO
- SPI_PA
- USB Type-C
- 5V
- VBUS_FTDI
- D11
- LDO
- POWER Source
- 3V3_FTDI
- M[2..0]
- DTR_RST
- BQ1
- PLS-8
- G1
- AREF
- AP2112K-3.3
- Clock
- 12MHz
- 25MHz
- CLKI
- XP10
- EEPROM
- QFN-88
- BE-U1000
- XS6
- XS1
- 93LC56BT
- PORT_B
- PB_IO
- QSPI_PB
- OTG
- DD3
- USB 2.0 HS OTG
- CC1
- CC2
- Controller
- TUSB320RWBR
- DD4
- I2C
- I2C2
- VBUS_MK_USB
- POWER
- SWITCH
- AP2191WG-7
- FLAG
- EN
- PC15
- PB14
- XP8
- XS3
- 3V3
- V_REF
- ZXRE160H5TA
- DD6
- 1V
- VREF
- 5V_EXT
- nRST_MCU
- VDD
- DD2
- BOOT_FLASH
- MT25QL128ABA3
- DD1
- QSPI
- QSPI1
- VIN
- DD10
- nRST_U
- nRST_ALL
- Reset Button
- SB2
- RES_BUT
- Logic
- NRESET
- PORT_C
- PC0
- User Led
- LD1
- PC_IO
- Supervisor
- DD9
- nSRST
- AND Gate
- SN74AC08
- PC13
- SB1
- User Button
- XS4
- TPS3838K33
- XP1
- VIN<0-7>
- ADC
- PC8
- PC4
- M2
- DBG_SEL
- STRAP
- Config Pins
- DC-DC
- DD12
- Jumper
- PWR
- DD13
- MOSI_1/PA10
- PB10
- M0
- M1
- 10-48V
- TPS54160DGQ
- 5V_INT
- Power 3V3 LED
- LD2

## Sheet EVU-BA-2.5_Sheet7.SchDoc: EVU-BA-2.5
size A3; SheetNumber: 7; SheetTotal: 7; Prj: EVU-BA; Ver: 2.5; Ti: Revision History
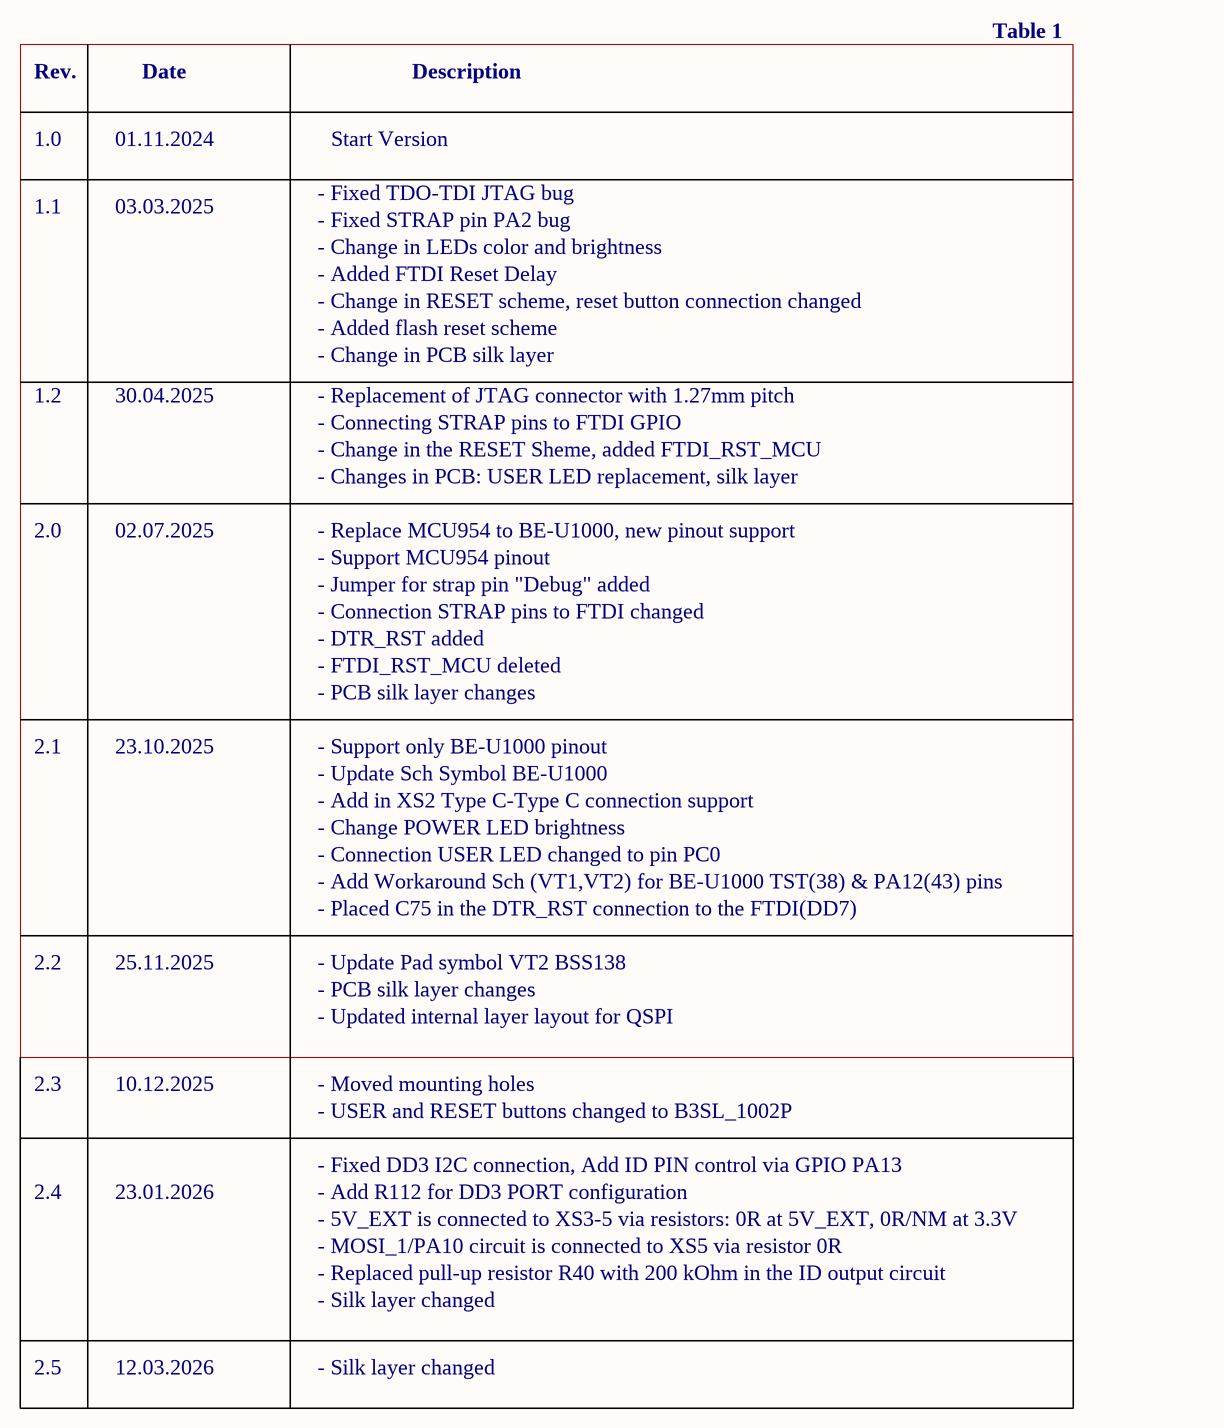
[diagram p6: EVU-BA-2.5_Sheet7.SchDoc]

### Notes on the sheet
- Table 1
- Rev.
- Date
- Description
- 1.0
- 01.11.2024
- - Fixed TDO-TDI JTAG bug
- Start Version
- 1.1
- 03.03.2025
- - Fixed STRAP pin PA2 bug
- - Change in LEDs color and brightness
- - Added FTDI Reset Delay
- - Change in RESET sсheme, reset button connection changed
- - Added flash reset scheme
- 1.2
- 30.04.2025
- - Replacement of JTAG connector with 1.27mm pitch
- - Change in PCB silk layer
- - Connecting STRAP pins to FTDI GPIO
- - Change in the RESET Sheme, added FTDI_RST_MCU
- 2.0
- 02.07.2025
- - Changes in PCB: USER LED replacement, silk layer
- - Replace MCU954 to BE-U1000, new pinout support
- - Support MCU954 pinout
- - Jumper for strap pin "Debug" added
- - Connection STRAP pins to FTDI changed
- - DTR_RST added
- - FTDI_RST_MCU deleted
- - PCB silk layer changes
- 2.1
- 23.10.2025
- - Support only BE-U1000 pinout
- - Update Sch Symbol BE-U1000
- - Add in XS2 Type C-Type C connection support
- - Change POWER LED brightness
- - Connection USER LED changed to pin PC0
- - Add Workaround Sch (VT1,VT2) for BE-U1000 TST(38) & PA12(43) pins
- - Placed C75 in the DTR_RST connection to the FTDI(DD7)
- 2.2
- 25.11.2025
- - Update Pad symbol VT2 BSS138
- - Updated internal layer layout for QSPI
- 2.3
- 10.12.2025
- - Moved mounting holes
- - USER and RESET buttons changed to B3SL_1002P
- 2.4
- 23.01.2026
- - Fixed DD3 I2C connection, Add ID PIN control via GPIO PA13
- - Add R112 for DD3 PORT configuration
- - 5V_EXT is connected to XS3-5 via resistors: 0R at 5V_EXT, 0R/NM at 3.3V
- - MOSI_1/PA10 circuit is connected to XS5 via resistor 0R
- - Replaced pull-up resistor R40 with 200 kOhm in the ID output circuit
- - Silk layer changed
- 2.5
- 12.03.2026

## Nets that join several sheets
3V3: EVU-BA-2.5_Sheet3 (R104.1 R117.1), EVU-BA-2.5_Sheet2 (34 pins), EVU-BA-2.5_Sheet4 (16 pins), EVU-BA-2.5_Sheet5 (C74.2 DD13.5 LD2.1)
3V3_FTDI: EVU-BA-2.5_Sheet3 (14 pins), EVU-BA-2.5_Sheet5 (C69.2 DD11.5)
5V: EVU-BA-2.5_Sheet3 (R99.2), EVU-BA-2.5_Sheet2 (5 pins), EVU-BA-2.5_Sheet5 (6 pins)
5V_EXT: EVU-BA-2.5_Sheet4 (R115.2 XP8.18), EVU-BA-2.5_Sheet5 (XP11.3)
GND: EVU-BA-2.5_Sheet3 (48 pins), EVU-BA-2.5_Sheet2 (70 pins), EVU-BA-2.5_Sheet4 (26 pins), EVU-BA-2.5_Sheet5 (22 pins)
AREF: EVU-BA-2.5_Sheet2 (R46.2), EVU-BA-2.5_Sheet4 (XP9.7 XS5.8)
CS_1/PA8: EVU-BA-2.5_Sheet2 (DD5.51), EVU-BA-2.5_Sheet4 (XP9.17 XS5.3)
DTR_RST: EVU-BA-2.5_Sheet3 (C75.1), EVU-BA-2.5_Sheet4 (DD10.13 R107.1)
I2C2_SCL/PB8: EVU-BA-2.5_Sheet2 (DD5.3 R33.2), EVU-BA-2.5_Sheet4 (XP10.13 XS6.3)
I2C2_SDA/PB9: EVU-BA-2.5_Sheet2 (DD5.2 R28.2), EVU-BA-2.5_Sheet4 (XP10.14)
M0: EVU-BA-2.5_Sheet3 (R102.2), EVU-BA-2.5_Sheet2 (R11.1 R18.1 XP1.9)
M1: EVU-BA-2.5_Sheet3 (R101.2), EVU-BA-2.5_Sheet2 (R10.1 R21.1 XP1.7)
M2: EVU-BA-2.5_Sheet3 (R100.2), EVU-BA-2.5_Sheet2 (R9.2 R20.1 XP1.5)
MISO_1/PA11: EVU-BA-2.5_Sheet2 (DD5.45), EVU-BA-2.5_Sheet4 (XP9.13 XS5.5)
MOSI_1/PA10: EVU-BA-2.5_Sheet2 (DD5.46 R11.2), EVU-BA-2.5_Sheet4 (R119.2 XP9.15)
nRESET: EVU-BA-2.5_Sheet3 (R56.1), EVU-BA-2.5_Sheet4 (DD9.4 R81.1 R84.2)
nRST_MCU: EVU-BA-2.5_Sheet2 (R8.1 R116.1), EVU-BA-2.5_Sheet4 (DD10.11)
nSRST: EVU-BA-2.5_Sheet3 (R68.2 XP6.10), EVU-BA-2.5_Sheet4 (R85.1)
nVBUS_FLG_USB/PB14: EVU-BA-2.5_Sheet2 (DD5.84 R36.2), EVU-BA-2.5_Sheet4 (XP10.9 XS6.5)
PA13: EVU-BA-2.5_Sheet2 (DD5.42 R114.1), EVU-BA-2.5_Sheet4 (XP9.19 XS5.1)
PA14: EVU-BA-2.5_Sheet2 (DD5.41), EVU-BA-2.5_Sheet4 (XP9.14)
PA15: EVU-BA-2.5_Sheet2 (DD5.39), EVU-BA-2.5_Sheet4 (XP9.16)
PB10: EVU-BA-2.5_Sheet2 (DD5.88 R10.2), EVU-BA-2.5_Sheet4 (XP10.16)
PC1: EVU-BA-2.5_Sheet2 (DD5.80), EVU-BA-2.5_Sheet4 (XP8.2)
PC2: EVU-BA-2.5_Sheet2 (DD5.79), EVU-BA-2.5_Sheet4 (XP8.3)
PC3: EVU-BA-2.5_Sheet2 (DD5.78), EVU-BA-2.5_Sheet4 (XP8.4)
PC4: EVU-BA-2.5_Sheet2 (DD5.75 R9.1), EVU-BA-2.5_Sheet4 (XP8.5)
PC5: EVU-BA-2.5_Sheet2 (DD5.74), EVU-BA-2.5_Sheet4 (XP8.6)
PC6: EVU-BA-2.5_Sheet2 (DD5.73 R108.1), EVU-BA-2.5_Sheet4 (XP8.7)
PC7: EVU-BA-2.5_Sheet2 (DD5.72), EVU-BA-2.5_Sheet4 (XP8.9)
PC8: EVU-BA-2.5_Sheet2 (DD5.70 R12.1), EVU-BA-2.5_Sheet4 (XP8.10)
PC9: EVU-BA-2.5_Sheet2 (DD5.69), EVU-BA-2.5_Sheet4 (XP8.11)
PC10: EVU-BA-2.5_Sheet2 (DD5.68), EVU-BA-2.5_Sheet4 (XP8.13)
PC11: EVU-BA-2.5_Sheet2 (DD5.67), EVU-BA-2.5_Sheet4 (XP8.15)
PC12: EVU-BA-2.5_Sheet2 (DD5.65), EVU-BA-2.5_Sheet4 (XP8.17)
PC13: EVU-BA-2.5_Sheet2 (DD5.64 R22.2), EVU-BA-2.5_Sheet4 (XP8.21)
PC14: EVU-BA-2.5_Sheet2 (DD5.63), EVU-BA-2.5_Sheet4 (XP8.23)
PC15: EVU-BA-2.5_Sheet2 (DD5.62 R43.2), EVU-BA-2.5_Sheet4 (XP8.25)
QSPI1_CS/PB0: EVU-BA-2.5_Sheet2 (R5.2 R53.2), EVU-BA-2.5_Sheet4 (XP10.1)
QSPI1_IO2/PB4: EVU-BA-2.5_Sheet2 (R3.2 R50.2), EVU-BA-2.5_Sheet4 (XP10.6)
QSPI1_IO3/PB5: EVU-BA-2.5_Sheet2 (R25.1 R51.2), EVU-BA-2.5_Sheet4 (XP10.8)
QSPI1_MISO/PB3: EVU-BA-2.5_Sheet2 (R7.2 R49.2), EVU-BA-2.5_Sheet4 (XP10.19)
QSPI1_MOSI/PB2: EVU-BA-2.5_Sheet2 (R27.1 R48.2), EVU-BA-2.5_Sheet4 (XP10.3 XS6.8)
QSPI1_SCK/PB1: EVU-BA-2.5_Sheet2 (R26.1 R47.2), EVU-BA-2.5_Sheet4 (XP10.2)
RX_3/PB7: EVU-BA-2.5_Sheet2 (DD5.4), EVU-BA-2.5_Sheet4 (XP10.17 XS6.1)
SCK_1/PA9: EVU-BA-2.5_Sheet2 (DD5.50), EVU-BA-2.5_Sheet4 (XP9.11 XS5.6)
SCL_0/PA4: EVU-BA-2.5_Sheet3 (R75.2), EVU-BA-2.5_Sheet2 (DD5.57), EVU-BA-2.5_Sheet4 (XP9.3 XS5.10)
SDA_0/PA5: EVU-BA-2.5_Sheet2 (DD5.56), EVU-BA-2.5_Sheet4 (XP9.5 XS5.9)
TCK/PA0: EVU-BA-2.5_Sheet3 (R76.2), EVU-BA-2.5_Sheet2 (DD5.61), EVU-BA-2.5_Sheet4 (XP9.1)
TDI/PA3: EVU-BA-2.5_Sheet3 (R72.2), EVU-BA-2.5_Sheet2 (DD5.58), EVU-BA-2.5_Sheet4 (XP9.6)
TDO/PA2: EVU-BA-2.5_Sheet3 (R73.2), EVU-BA-2.5_Sheet2 (DD5.59), EVU-BA-2.5_Sheet4 (XP9.4)
TIM0_PWM0/PA12: EVU-BA-2.5_Sheet2 (DD5.43 VT2.3), EVU-BA-2.5_Sheet4 (XP9.18 XS5.2)
TIM1_PWM0/PB12: EVU-BA-2.5_Sheet2 (DD5.86), EVU-BA-2.5_Sheet4 (XP10.5 XS6.7)
TIM1_PWM1/PB13: EVU-BA-2.5_Sheet2 (DD5.85), EVU-BA-2.5_Sheet4 (XP10.7 XS6.6)
TIM1_PWM3/PB15: EVU-BA-2.5_Sheet2 (DD5.83), EVU-BA-2.5_Sheet4 (XP10.11 XS6.4)
TMS/PA1: EVU-BA-2.5_Sheet3 (R74.2), EVU-BA-2.5_Sheet2 (DD5.60), EVU-BA-2.5_Sheet4 (XP9.2)
TUSB_INT/PB11: EVU-BA-2.5_Sheet2 (DD5.87 R34.2 R39.2), EVU-BA-2.5_Sheet4 (XP10.18)
TX_3/PB6: EVU-BA-2.5_Sheet2 (DD5.5), EVU-BA-2.5_Sheet4 (XP10.15 XS6.2)
UART0_RX/PA7: EVU-BA-2.5_Sheet3 (R106.2), EVU-BA-2.5_Sheet2 (DD5.52), EVU-BA-2.5_Sheet4 (XP9.10)
UART0_TX/PA6: EVU-BA-2.5_Sheet3 (R105.2), EVU-BA-2.5_Sheet2 (DD5.53), EVU-BA-2.5_Sheet4 (XP9.8)
USER_LED/PC0: EVU-BA-2.5_Sheet2 (DD5.81), EVU-BA-2.5_Sheet4 (LD1.1 XP8.1)
VBUS_FTDI: EVU-BA-2.5_Sheet3 (C41.1 DD15.5 L10.2), EVU-BA-2.5_Sheet5 (C66.2 D6.2 DD11.1 R90.1)
VBUS_MK_USB: EVU-BA-2.5_Sheet2 (7 pins), EVU-BA-2.5_Sheet5 (D7.2)
VIN: EVU-BA-2.5_Sheet4 (XP8.24 XS3.8), EVU-BA-2.5_Sheet5 (FU1.1)
VIN<0>: EVU-BA-2.5_Sheet2 (DD5.23), EVU-BA-2.5_Sheet4 (XP8.28 XS4.1)
VIN<1>: EVU-BA-2.5_Sheet2 (DD5.24), EVU-BA-2.5_Sheet4 (XP8.30 XS4.2)
VIN<2>: EVU-BA-2.5_Sheet2 (DD5.25), EVU-BA-2.5_Sheet4 (XP8.32 XS4.3)
VIN<3>: EVU-BA-2.5_Sheet2 (DD5.26), EVU-BA-2.5_Sheet4 (XP8.34 XS4.4)
VIN<4>: EVU-BA-2.5_Sheet2 (DD5.30), EVU-BA-2.5_Sheet4 (XP8.36 XS4.5)
VIN<5>: EVU-BA-2.5_Sheet2 (DD5.31), EVU-BA-2.5_Sheet4 (XP8.38 XS4.6)
VIN<6>: EVU-BA-2.5_Sheet2 (DD5.32), EVU-BA-2.5_Sheet4 (XP8.35)
VIN<7>: EVU-BA-2.5_Sheet2 (DD5.33), EVU-BA-2.5_Sheet4 (XP8.37)

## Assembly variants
EVU-BA-2.5: not fitted C59 C75 R2 R6 R13 R15 R17 R23 R32 R41 R44 R46 R77 R99 R100 R101 R102 R112 R114 R118 XP2 XP3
